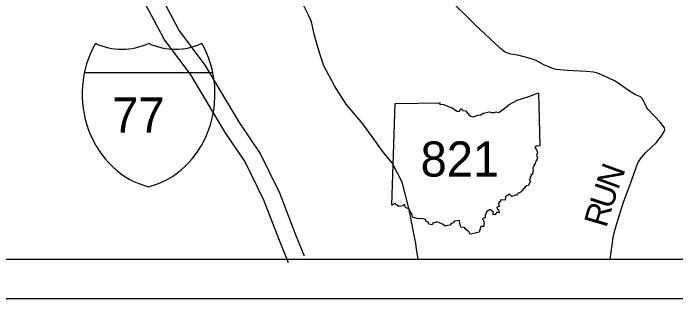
# Model space of a CAD drawing. Extents: x 0 to 34, y 0 to 22.
# Drawn here: x 25.646 to 27.239, y 9.524 to 10.21 of the extents above; entities that cross this region are included whole.
import ezdxf

# ---------------------------------------------------------------- set-up
doc = ezdxf.new("R2010")
doc.units = 0
for name, color, linetype in [('Default', 7, 'Continuous'), ('GM_X_County_Road_Text', 7, 'Continuous'), ('GM_X_Major_River', 7, 'Continuous'), ('GM_X_State_Route', 7, 'Continuous')]:
    doc.layers.add(name, color=color, linetype=linetype)

msp = doc.modelspace()

# ---------------------------------------------------------------- linework, layer by layer
at = {"layer": 'Default'}
for p, q in [((26.5561, 9.749), (26.564, 9.9931)), ((30.697, 9.6182), (19.8526, 9.6182))]:
    msp.add_line(p, q, dxfattribs=at)
msp.add_lwpolyline([(19.7581, 20.557), (30.7915, 20.557), (30.7915, 9.5237), (19.7581, 9.5237)], close=True, dxfattribs=at)
for points in [[(27.2127, 9.9298), (27.2127, 9.9298), (27.2115, 9.9347), (27.2009, 9.948), (27.1718, 9.9797), (27.1676, 9.9858), (27.1639, 9.9933), (27.1608, 9.9998), (27.1578, 10.0054), (27.154, 10.0092), (27.1415, 10.0141), (27.1249, 10.0247), (27.1, 10.0421), (27.0913, 10.0477), (27.0659, 10.0594), (27.0508, 10.0658), (27.041, 10.0685), (27.0244, 10.0703), (26.9775, 10.0725), (26.9514, 10.0751), (26.9405, 10.0778), (26.9216, 10.0861), (26.903, 10.0963), (26.886, 10.1019), (26.8588, 10.1098), (26.8422, 10.1121), (26.8327, 10.1147), (26.829, 10.1158), (26.8169, 10.1257), (26.7556, 10.1835), (26.6917, 10.2473)], [(26.564, 9.9931), (26.6722, 9.9946), (26.6705, 9.9917), (26.6807, 9.9911), (26.6915, 9.9858), (26.7007, 9.9826), (26.7119, 9.9748), (26.7186, 9.9749), (26.7215, 9.9813), (26.7266, 9.9763), (26.7327, 9.9755), (26.7433, 9.9638), (26.752, 9.9613), (26.7625, 9.9653), (26.7702, 9.9659), (26.7759, 9.9699), (26.7907, 9.9733), (26.7949, 9.9712), (26.8028, 9.9717), (26.8068, 9.9731), (26.8136, 9.9718), (26.8256, 9.9807), (26.838, 9.9911), (26.8572, 10.001), (26.8857, 10.0103), (26.9083, 10.0187), (26.9115, 9.8921)], [(27.0808, 9.6182), (27.0882, 9.6708), (27.0916, 9.6852), (27.1002, 9.7147), (27.1138, 9.7582), (27.1289, 9.7988), (27.1473, 9.8503), (27.1556, 9.8628), (27.1666, 9.8753), (27.1923, 9.8995), (27.2059, 9.9181), (27.2108, 9.9257), (27.2127, 9.9298)], [(26.9115, 9.8921), (26.9082, 9.8903), (26.903, 9.8911), (26.8996, 9.8876), (26.9039, 9.8817), (26.9059, 9.8754), (26.9041, 9.8685), (26.9059, 9.8628), (26.9047, 9.8581), (26.9014, 9.8533), (26.9003, 9.8488), (26.8975, 9.844), (26.8977, 9.8414), (26.8951, 9.8393), (26.8956, 9.8313), (26.8942, 9.827), (26.8947, 9.8232), (26.8904, 9.8222), (26.8914, 9.8191), (26.8887, 9.8166), (26.8893, 9.8125), (26.8861, 9.8098), (26.8891, 9.8045), (26.8867, 9.8028), (26.8847, 9.7964), (26.8792, 9.795), (26.8683, 9.7833), (26.8644, 9.7788), (26.86, 9.7777), (26.8576, 9.7731), (26.8523, 9.7731), (26.8441, 9.7699), (26.8388, 9.7753), (26.8296, 9.7688), (26.8286, 9.7611), (26.817, 9.7614), (26.8174, 9.7575), (26.8148, 9.7564), (26.8125, 9.7526), (26.8138, 9.7457), (26.8084, 9.744), (26.809, 9.74), (26.8125, 9.7376), (26.8141, 9.73), (26.8083, 9.7315), (26.8036, 9.7251), (26.7986, 9.7266), (26.8002, 9.732), (26.792, 9.7386), (26.7842, 9.7334), (26.7801, 9.725), (26.7801, 9.7193), (26.7742, 9.716), (26.778, 9.708), (26.7773, 9.7026), (26.7774, 9.6973), (26.7702, 9.6976), (26.7657, 9.6835)], [(26.7657, 9.6835), (26.7531, 9.6809), (26.7444, 9.6793), (26.7413, 9.6856), (26.735, 9.689), (26.7309, 9.6954), (26.7219, 9.6962), (26.7198, 9.7051), (26.7188, 9.7122), (26.7065, 9.7104), (26.7032, 9.7061), (26.6988, 9.7049), (26.6963, 9.7005), (26.6903, 9.7001), (26.6839, 9.698), (26.6797, 9.7023), (26.6692, 9.7067), (26.6645, 9.7089), (26.6547, 9.7055), (26.6526, 9.7014), (26.6448, 9.7032), (26.643, 9.7078), (26.6382, 9.7092), (26.6372, 9.714), (26.6271, 9.7166), (26.6193, 9.7156), (26.6056, 9.7195), (26.6048, 9.7259), (26.6001, 9.7337), (26.5978, 9.7391), (26.5891, 9.7432), (26.5873, 9.7496), (26.5846, 9.7494), (26.5821, 9.7468), (26.5724, 9.7456), (26.5687, 9.7482), (26.5633, 9.7528), (26.5561, 9.749)]]:
    msp.add_lwpolyline(points, dxfattribs=at)
for centre, major_axis, start_param, end_param in [((26.0174, 10.016), (0, -0.2289), 4.15077, 6.05619), ((25.9071, 10.3061), (0, -0.1826), 5.88324, 6.683049), ((25.9247, 10.016), (0, -0.2289), 0.227007, 2.13242), ((26.0351, 10.3062), (0, -0.1827), 5.883359, 6.683012)]:
    msp.add_ellipse(centre, major_axis=major_axis, ratio=0.9, start_param=start_param, end_param=end_param, dxfattribs=at)
at = {"layer": 'GM_X_Major_River'}
msp.add_line((25.8172, 10.0675), (26.1254, 10.0675), dxfattribs=at)
at = {"layer": 'GM_X_State_Route'}
for points in [[(26.3457, 9.6259), (26.3244, 9.6791), (26.2863, 9.7773), (26.2391, 9.8739), (26.1898, 9.9475), (26.1069, 10.0851), (26.0437, 10.1703), (25.9851, 10.2816), (25.9607, 10.3449), (25.9469, 10.4375)], [(26.3071, 9.6104), (26.2857, 9.6638), (26.2481, 9.7607), (26.2029, 9.8531), (26.1547, 9.9252), (26.0723, 10.0619), (26.0083, 10.1481), (25.9471, 10.2644), (25.9203, 10.3342), (25.9058, 10.4314)], [(26.6155, 9.6437), (26.6136, 9.6569), (26.5965, 9.7412), (26.5809, 9.8044), (26.5567, 9.8509), (26.5356, 9.8752), (26.4861, 9.9447), (26.4462, 9.9919), (26.4184, 10.0357), (26.3925, 10.0841), (26.3823, 10.1152), (26.3734, 10.1453), (26.3702, 10.1564), (26.3626, 10.1893), (26.3558, 10.2056), (26.3312, 10.2548), (26.3111, 10.2858), (26.2767, 10.3179), (26.2457, 10.3462)], [(26.6192, 9.6182), (26.6155, 9.6437)]]:
    msp.add_lwpolyline(points, dxfattribs=at)

# ---------------------------------------------------------------- texts
at = {"layer": 'Default'}
for s, p in [('77', (25.8836, 9.9232)), ('821', (26.6251, 9.8174))]:
    msp.add_text(s, height=0.08462, dxfattribs=at).set_placement(p)
at = {"layer": 'GM_X_County_Road_Text'}
for s, rotation, p in [('N', 69.898, (27.0999, 9.7838)), ('U', 71.8254, (27.0846, 9.7368)), ('R', 73.6884, (27.0716, 9.6926))]:
    msp.add_text(s, height=0.0567, rotation=rotation, dxfattribs=at).set_placement(p)

doc.saveas('drawing.dxf')
